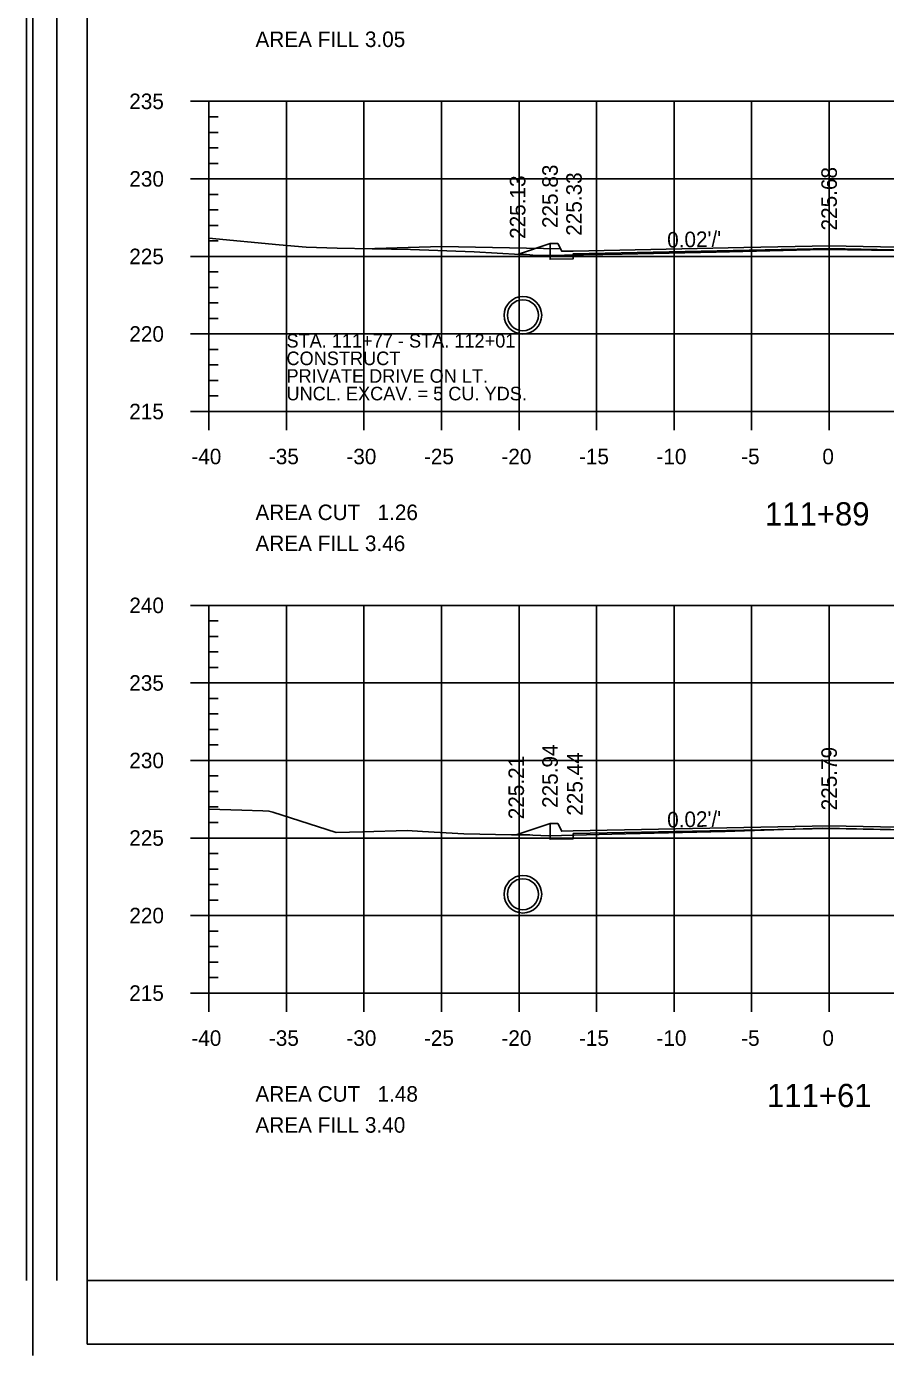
# Model space of a CAD drawing. Extents: x 1367903 to 1373764, y 376865 to 382130.
# Drawn here: x 1372830.3 to 1372941.1, y 377279.1 to 377450.5 of the extents above; entities that cross this region are included whole.
import ezdxf

# ---------------------------------------------------------------- set-up
doc = ezdxf.new("R2010")
doc.units = 0
for name, color, linetype in [('R_Axis', 7, 'Continuous'), ('R_Axis Annot', 7, 'Continuous'), ('R_Border', 7, 'Continuous'), ('R_Border PE', 7, 'Continuous'), ('R_Draft', 7, 'Continuous'), ('R_Drive', 7, 'Continuous'), ('R_Exist Surface', 7, 'Continuous'), ('R_Fin Surface', 7, 'Continuous'), ('R_Fin Surface Annot', 7, 'Continuous'), ('R_Grid', 7, 'Continuous'), ('R_Water', 7, 'Continuous')]:
    doc.layers.add(name, color=color, linetype=linetype)

msp = doc.modelspace()

# ---------------------------------------------------------------- linework, layer by layer
for points in [[(1372897.8, 377422.5), (1372897.8, 377421.83), (1372897.8, 377421.83), (1372897.8, 377420.47), (1372900.8, 377420.53), (1372900.8, 377421.19), (1372933.8, 377421.85), (1372966.8, 377421.19), (1372966.8, 377420.53), (1372969.8, 377420.47), (1372969.8, 377421.91), (1372983.8, 377422.19), (1372983.8, 377422.78)], [(1372897.8, 377347.72), (1372897.8, 377347.05), (1372897.8, 377347.05), (1372897.8, 377345.69), (1372900.8, 377345.75), (1372900.8, 377346.41), (1372933.8, 377347.07), (1372966.8, 377346.41), (1372966.8, 377345.75), (1372969.8, 377345.69), (1372969.8, 377347.13), (1372983.8, 377347.41), (1372983.8, 377348)]]:
    msp.add_lwpolyline(points)
at = {"layer": 'R_Axis'}
for p, q in [((1372851.4, 377440.84), (1372856.2, 377440.84)), ((1372853.8, 377400.84), (1372853.8, 377440.84)), ((1372853.8, 377438.84), (1372855, 377438.84)), ((1372853.8, 377436.84), (1372855, 377436.84)), ((1372853.8, 377434.84), (1372855, 377434.84)), ((1372853.8, 377432.84), (1372855, 377432.84)), ((1372851.4, 377430.84), (1372856.2, 377430.84)), ((1372853.8, 377428.84), (1372855, 377428.84)), ((1372853.8, 377426.84), (1372855, 377426.84)), ((1372853.8, 377424.84), (1372855, 377424.84)), ((1372853.8, 377422.84), (1372855, 377422.84)), ((1372851.4, 377420.84), (1372856.2, 377420.84)), ((1372853.8, 377418.84), (1372855, 377418.84)), ((1372853.8, 377416.84), (1372855, 377416.84)), ((1372853.8, 377414.84), (1372855, 377414.84)), ((1372853.8, 377412.84), (1372855, 377412.84)), ((1372851.4, 377410.84), (1372856.2, 377410.84)), ((1372853.8, 377408.84), (1372855, 377408.84)), ((1372853.8, 377406.84), (1372855, 377406.84)), ((1372853.8, 377404.84), (1372855, 377404.84)), ((1372853.8, 377398.44), (1372853.8, 377403.24)), ((1372863.8, 377398.44), (1372863.8, 377403.24)), ((1372873.8, 377398.44), (1372873.8, 377403.24)), ((1372883.8, 377398.44), (1372883.8, 377403.24)), ((1372893.8, 377398.44), (1372893.8, 377403.24)), ((1372903.8, 377398.44), (1372903.8, 377403.24)), ((1372913.8, 377398.44), (1372913.8, 377403.24)), ((1372923.8, 377398.44), (1372923.8, 377403.24)), ((1372933.8, 377398.44), (1372933.8, 377403.24)), ((1372853.8, 377402.84), (1372855, 377402.84)), ((1372851.4, 377400.84), (1372856.2, 377400.84)), ((1372853.8, 377400.84), (1373013.8, 377400.84)), ((1372851.4, 377375.84), (1372856.2, 377375.84)), ((1372853.8, 377325.84), (1372853.8, 377375.84)), ((1372853.8, 377373.84), (1372855, 377373.84)), ((1372853.8, 377371.84), (1372855, 377371.84)), ((1372853.8, 377369.84), (1372855, 377369.84)), ((1372853.8, 377367.84), (1372855, 377367.84)), ((1372851.4, 377365.84), (1372856.2, 377365.84)), ((1372853.8, 377363.84), (1372855, 377363.84)), ((1372853.8, 377361.84), (1372855, 377361.84)), ((1372853.8, 377359.84), (1372855, 377359.84)), ((1372853.8, 377357.84), (1372855, 377357.84)), ((1372851.4, 377355.84), (1372856.2, 377355.84)), ((1372853.8, 377353.84), (1372855, 377353.84)), ((1372853.8, 377351.84), (1372855, 377351.84)), ((1372853.8, 377349.84), (1372855, 377349.84)), ((1372853.8, 377347.84), (1372855, 377347.84)), ((1372851.4, 377345.84), (1372856.2, 377345.84)), ((1372853.8, 377343.84), (1372855, 377343.84)), ((1372853.8, 377341.84), (1372855, 377341.84)), ((1372853.8, 377339.84), (1372855, 377339.84)), ((1372853.8, 377337.84), (1372855, 377337.84)), ((1372851.4, 377335.84), (1372856.2, 377335.84)), ((1372853.8, 377333.84), (1372855, 377333.84)), ((1372853.8, 377331.84), (1372855, 377331.84)), ((1372853.8, 377329.84), (1372855, 377329.84)), ((1372853.8, 377323.44), (1372853.8, 377328.24)), ((1372853.8, 377327.84), (1372855, 377327.84)), ((1372863.8, 377323.44), (1372863.8, 377328.24)), ((1372873.8, 377323.44), (1372873.8, 377328.24)), ((1372883.8, 377323.44), (1372883.8, 377328.24)), ((1372893.8, 377323.44), (1372893.8, 377328.24)), ((1372903.8, 377323.44), (1372903.8, 377328.24)), ((1372913.8, 377323.44), (1372913.8, 377328.24)), ((1372923.8, 377323.44), (1372923.8, 377328.24)), ((1372933.8, 377323.44), (1372933.8, 377328.24)), ((1372851.4, 377325.84), (1372856.2, 377325.84)), ((1372853.8, 377325.84), (1373013.8, 377325.84))]:
    msp.add_line(p, q, dxfattribs=at)
at = {"layer": 'R_Border'}
for p, q in [((1372831.08, 377620.35), (1372831.08, 377279.12)), ((1372838.11, 377611.47), (1372838.11, 377280.59)), ((1372838.11, 377280.59), (1373042.43, 377280.59))]:
    msp.add_line(p, q, dxfattribs=at)
at = {"layer": 'R_Border PE'}
for p, q in [((1372830.27, 377610.76), (1372830.27, 377288.8)), ((1372834.19, 377610.76), (1372834.19, 377288.8)), ((1372838.11, 377288.8), (1372838.11, 377603.25)), ((1372838.11, 377288.8), (1373042.43, 377288.8))]:
    msp.add_line(p, q, dxfattribs=at)
at = {"layer": 'R_Drive'}
for q in [(1372873.8, 377421.82), (1372899.13, 377421.83)]:
    msp.add_line((1372883.8, 377422.14), q, dxfattribs=at)
at = {"layer": 'R_Exist Surface'}
for points in [[(1372853.8, 377423.21), (1372862.85, 377422.34), (1372866.35, 377422.02), (1372870.34, 377421.91), (1372874.85, 377421.8), (1372879.8, 377421.72), (1372888.03, 377421.44), (1372893.94, 377421.08), (1372894.78, 377421.1), (1372896.02, 377420.94), (1372897.17, 377420.94), (1372907.11, 377421.12), (1372919.25, 377421.37), (1372933.06, 377421.73), (1372960.89, 377421.36)], [(1372853.8, 377349.58), (1372858.02, 377349.44), (1372860.77, 377349.35), (1372861.53, 377349.31), (1372862.02, 377349.19), (1372870.2, 377346.56), (1372873.63, 377346.63), (1372879.35, 377346.83), (1372881.33, 377346.7), (1372886.66, 377346.4), (1372892.83, 377346.26), (1372895.19, 377346.27), (1372895.56, 377346.22), (1372897.63, 377346.12), (1372905.78, 377346.33), (1372920.37, 377346.7), (1372932.95, 377347.09), (1372954.92, 377346.69)]]:
    msp.add_lwpolyline(points, dxfattribs=at)
at = {"layer": 'R_Fin Surface'}
for points in [[(1372893.62, 377421.1), (1372897.8, 377422.5), (1372898.8, 377422.5), (1372899.3, 377421.5), (1372900.8, 377421.53), (1372922.8, 377421.97), (1372933.8, 377422.19), (1372944.8, 377421.97), (1372966.8, 377421.53), (1372968.3, 377421.5), (1372968.8, 377422.5), (1372969.8, 377422.5), (1372973.8, 377422.58), (1372983.8, 377422.78), (1372985.32, 377422.27)], [(1372893.44, 377346.26), (1372897.8, 377347.72), (1372898.8, 377347.72), (1372899.3, 377346.72), (1372900.8, 377346.75), (1372922.8, 377347.19), (1372933.8, 377347.41), (1372944.8, 377347.19), (1372966.8, 377346.75), (1372968.3, 377346.72), (1372968.8, 377347.72), (1372969.8, 377347.72), (1372973.8, 377347.8), (1372983.8, 377348), (1372984.96, 377347.61)]]:
    msp.add_lwpolyline(points, dxfattribs=at)
at = {"layer": 'R_Grid'}
for p, q in [((1372853.8, 377440.84), (1373013.8, 377440.84)), ((1372853.8, 377400.84), (1372853.8, 377440.84)), ((1372863.8, 377400.84), (1372863.8, 377440.84)), ((1372873.8, 377400.84), (1372873.8, 377440.84)), ((1372883.8, 377400.84), (1372883.8, 377440.84)), ((1372893.8, 377400.84), (1372893.8, 377440.84)), ((1372903.8, 377400.84), (1372903.8, 377440.84)), ((1372913.8, 377400.84), (1372913.8, 377440.84)), ((1372923.8, 377400.84), (1372923.8, 377440.84)), ((1372933.8, 377400.84), (1372933.8, 377440.84)), ((1372853.8, 377430.84), (1373013.8, 377430.84)), ((1372853.8, 377420.84), (1373013.8, 377420.84)), ((1372853.8, 377410.84), (1373013.8, 377410.84)), ((1372853.8, 377400.84), (1373013.8, 377400.84)), ((1372853.8, 377375.84), (1373013.8, 377375.84)), ((1372853.8, 377325.84), (1372853.8, 377375.84)), ((1372863.8, 377325.84), (1372863.8, 377375.84)), ((1372873.8, 377325.84), (1372873.8, 377375.84)), ((1372883.8, 377325.84), (1372883.8, 377375.84)), ((1372893.8, 377325.84), (1372893.8, 377375.84)), ((1372903.8, 377325.84), (1372903.8, 377375.84)), ((1372913.8, 377325.84), (1372913.8, 377375.84)), ((1372923.8, 377325.84), (1372923.8, 377375.84)), ((1372933.8, 377325.84), (1372933.8, 377375.84)), ((1372853.8, 377365.84), (1373013.8, 377365.84)), ((1372853.8, 377355.84), (1373013.8, 377355.84)), ((1372853.8, 377345.84), (1373013.8, 377345.84)), ((1372853.8, 377335.84), (1373013.8, 377335.84)), ((1372853.8, 377325.84), (1373013.8, 377325.84))]:
    msp.add_line(p, q, dxfattribs=at)
at = {"layer": 'R_Water'}
for p, q in [((1372894.3, 377415.69), (1372894.3, 377415.64)), ((1372894.3, 377415.27), (1372894.3, 377415.23)), ((1372894.3, 377411.27), (1372894.3, 377411.23)), ((1372894.3, 377410.86), (1372894.3, 377410.81)), ((1372894.3, 377341.03), (1372894.3, 377340.98)), ((1372894.3, 377340.61), (1372894.3, 377340.56)), ((1372894.3, 377336.61), (1372894.3, 377336.56)), ((1372894.3, 377336.2), (1372894.3, 377336.15))]:
    msp.add_line(p, q, dxfattribs=at)
for centre, radius in [((1372894.3, 377413.25), 2.42), ((1372894.3, 377413.25), 2), ((1372894.3, 377338.59), 2.42), ((1372894.3, 377338.59), 2)]:
    msp.add_circle(centre, radius, dxfattribs=at)

# ---------------------------------------------------------------- texts
at = {"layer": 'R_Axis Annot'}
for s, height, p in [('AREA FILL 3.05', 2, (1372859.8, 377447.84)), ('235', 2, (1372843.52, 377439.84)), ('230', 2, (1372843.53, 377429.84)), ('225', 2, (1372843.52, 377419.84)), ('220', 2, (1372843.53, 377409.84)), ('215', 2, (1372843.52, 377399.84)), ('-40', 2, (1372851.53, 377394.04)), ('-35', 2, (1372861.53, 377394.04)), ('-30', 2, (1372871.53, 377394.04)), ('-25', 2, (1372881.53, 377394.04)), ('-20', 2, (1372891.53, 377394.04)), ('-15', 2, (1372901.53, 377394.04)), ('-10', 2, (1372911.53, 377394.04)), ('-5', 2, (1372922.46, 377394.04)), ('0', 2, (1372932.93, 377394.04)), ('AREA CUT   1.26', 2, (1372859.8, 377386.84)), ('111+89', 3, (1372925.52, 377386.14)), ('AREA FILL 3.46', 2, (1372859.8, 377382.84)), ('240', 2, (1372843.53, 377374.84)), ('235', 2, (1372843.52, 377364.84)), ('230', 2, (1372843.53, 377354.84)), ('225', 2, (1372843.52, 377344.84)), ('220', 2, (1372843.53, 377334.84)), ('215', 2, (1372843.52, 377324.84)), ('-40', 2, (1372851.53, 377319.04)), ('-35', 2, (1372861.53, 377319.04)), ('-30', 2, (1372871.53, 377319.04)), ('-25', 2, (1372881.53, 377319.04)), ('-20', 2, (1372891.53, 377319.04)), ('-15', 2, (1372901.53, 377319.04)), ('-10', 2, (1372911.53, 377319.04)), ('-5', 2, (1372922.46, 377319.04)), ('0', 2, (1372932.93, 377319.04)), ('111+61', 3, (1372925.79, 377311.14)), ('AREA CUT   1.48', 2, (1372859.8, 377311.84)), ('AREA FILL 3.40', 2, (1372859.8, 377307.84))]:
    msp.add_text(s, height=height, dxfattribs=at).set_placement(p)
at = {"layer": 'R_Draft'}
for s, p in [('STA. 111+77 - STA. 112+01', (1372863.8, 377409.09)), ('CONSTRUCT', (1372863.8, 377406.82)), ('PRIVATE DRIVE ON LT.', (1372863.8, 377404.55)), ('UNCL. EXCAV. = 5 CU. YDS.', (1372863.8, 377402.28))]:
    msp.add_text(s, height=1.75, dxfattribs=at).set_placement(p)
at = {"layer": 'R_Fin Surface Annot'}
for s, rotation, p in [('225.83', 90, (1372898.8, 377424.5)), ('225.13', 90, (1372894.62, 377423.1)), ('225.33', 90, (1372901.89, 377423.5)), ('225.68', 90, (1372934.8, 377424.19)), ("0.02'/'", 1.1458, (1372912.93, 377421.97)), ('225.94', 90, (1372898.8, 377349.72)), ('225.79', 90, (1372934.8, 377349.41)), ('225.21', 90, (1372894.44, 377348.26)), ('225.44', 90, (1372901.99, 377348.72)), ("0.02'/'", 1.1458, (1372912.93, 377347.19))]:
    msp.add_text(s, height=2, rotation=rotation, dxfattribs=at).set_placement(p)

doc.saveas('drawing.dxf')
